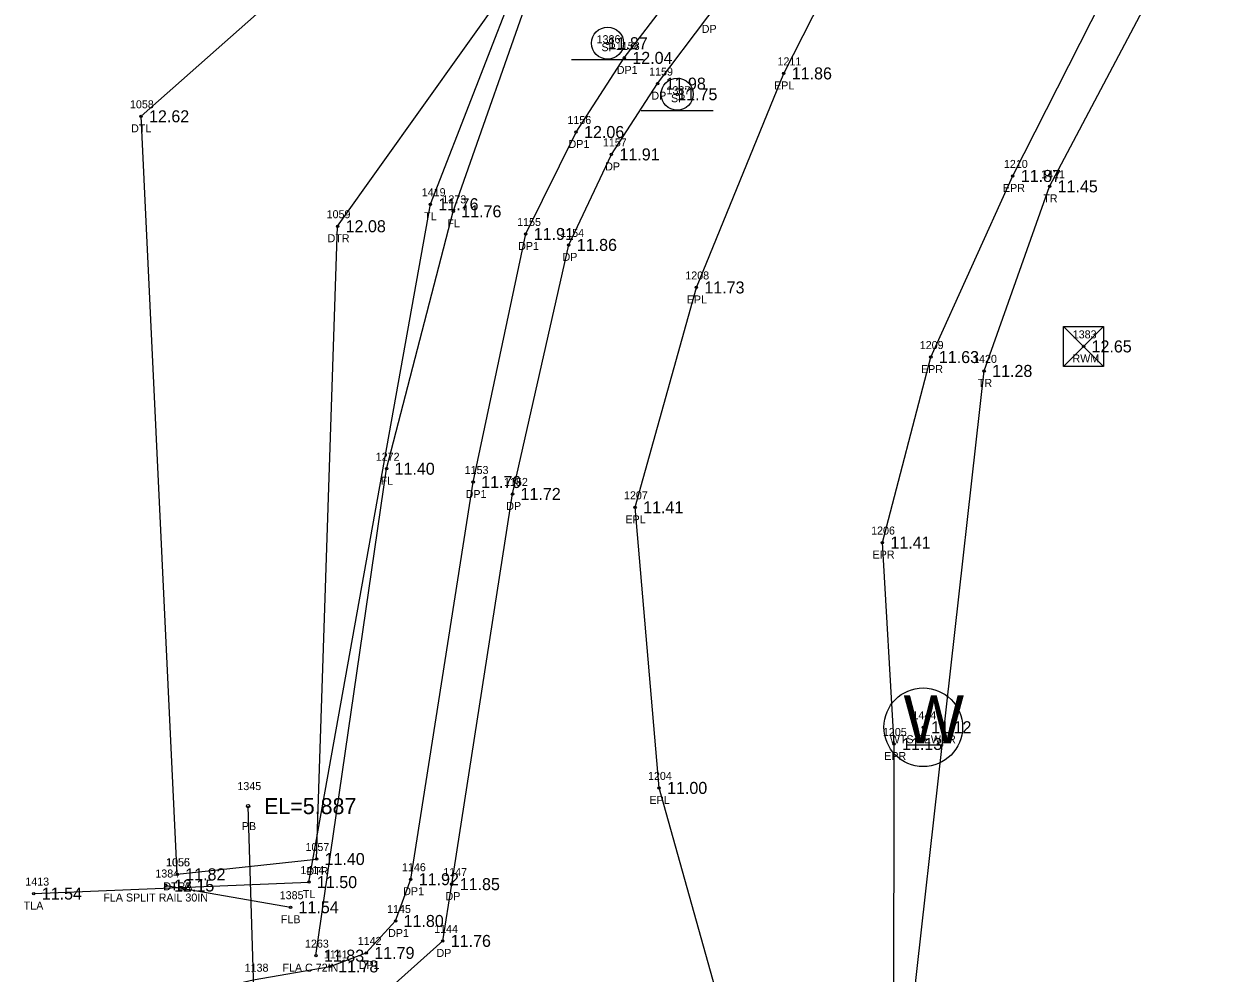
# Model space of a CAD drawing. Extents: x 2072307 to 2072993, y 127574 to 129736.
# Drawn here: x 2072680.7 to 2072830.3, y 128354.3 to 128472.9 of the extents above; entities that cross this region are included whole.
import ezdxf

# ---------------------------------------------------------------- set-up
doc = ezdxf.new("R2010")
doc.units = 0
for name, color, linetype in [('RD_EX_BldgApp', 7, 'Continuous'), ('RD_EX_BldgApp_txCode', 7, 'Continuous'), ('RD_EX_DR_Pipe', 7, 'Continuous'), ('RD_EX_DR_Pipe_txCode', 7, 'Continuous'), ('RD_EX_Driveway', 7, 'Continuous'), ('RD_EX_Driveway_txCode', 7, 'Continuous'), ('RD_EX_Fence_Other', 7, 'Continuous'), ('RD_EX_Fence_Other_txCode', 7, 'Continuous'), ('RD_EX_H2O', 7, 'Continuous'), ('RD_EX_H2O_txCode', 7, 'Continuous'), ('RD_EX_Road', 7, 'Continuous'), ('RD_EX_Road_txCode', 7, 'Continuous'), ('RD_EX_RW', 7, 'Continuous'), ('RD_EX_RW_TxCode', 7, 'Continuous'), ('RD_EX_TX_BldgApp_ELEV', 7, 'Continuous'), ('RD_EX_TX_Driveway_ELEV', 7, 'Continuous'), ('RD_EX_TX_Fence_Other_ELEV', 7, 'Continuous'), ('RD_EX_TX_H2O_ELEV', 7, 'Continuous'), ('RD_EX_TX_Road_ELEV', 7, 'Continuous'), ('RD_EX_TX_RW_ELEV', 7, 'Continuous'), ('RD_EX_TX_UT_ELEV', 7, 'Continuous'), ('RD_EX_TX_VEG_ELEV', 7, 'Continuous'), ('RD_EX_UT', 7, 'Continuous'), ('RD_EX_UT_txCode', 7, 'Continuous'), ('RD_EX_VEG', 7, 'Continuous'), ('RD_EX_VEG_txCode', 7, 'Continuous'), ('RD_SMD_Locator', 7, 'Continuous'), ('RD_TX_Pipe_ElevEX', 7, 'Continuous')]:
    doc.layers.add(name, color=color, linetype=linetype)

msp = doc.modelspace()

# ---------------------------------------------------------------- linework, layer by layer
at = {"layer": 'RD_EX_BldgApp'}
for p, q in [((2072749.16, 128468.44), (2072758.16, 128468.44)), ((2072757.86, 128462.07), (2072766.86, 128462.07))]:
    msp.add_line(p, q, dxfattribs=at)
for centre in [(2072753.67, 128470.46), (2072762.37, 128464.09)]:
    msp.add_circle(centre, 2, dxfattribs=at)
at = {"layer": 'RD_EX_DR_Pipe'}
msp.add_line((2072711.77, 128278.7), (2072708.75, 128375.17), dxfattribs=at)
at = {"layer": 'RD_EX_Driveway'}
for points in [[(2072694.21, 128239.74), (2072695.7, 128289.15), (2072695.56, 128330.43), (2072696.37, 128337.85), (2072700.81, 128345.17), (2072711.22, 128347.96), (2072719.56, 128349.59), (2072725.15, 128351.26), (2072733.07, 128358.33), (2072734.19, 128365.42), (2072741.79, 128414.16), (2072748.82, 128445.27), (2072754.15, 128456.57), (2072759.92, 128465.41), (2072766.21, 128473.75), (2072780.47, 128491.8), (2072796.27, 128516), (2072809.9, 128540.1), (2072821.01, 128555.78)], [(2072689.37, 128239.9), (2072690.93, 128289.43), (2072690.32, 128330.24), (2072690.73, 128338.81), (2072697.63, 128350.77), (2072709.38, 128353.48), (2072719, 128355.15), (2072723.52, 128356.83), (2072727.18, 128360.82), (2072729.07, 128366.04), (2072736.87, 128415.65), (2072743.44, 128446.63), (2072749.73, 128459.37), (2072755.76, 128468.63), (2072761.76, 128476.56), (2072776.61, 128495.01), (2072792.09, 128518.96), (2072805.19, 128542.59), (2072810.66, 128554.44), (2072797.46, 128551.01)]]:
    msp.add_lwpolyline(points, dxfattribs=at)
at = {"layer": 'RD_EX_Fence_Other'}
msp.add_line((2072698.5, 128365.25), (2072714.05, 128362.54), dxfattribs=at)
msp.add_lwpolyline([(2072717.23, 128356.49), (2072726.05, 128417.31), (2072734.38, 128449.46), (2072744.93, 128479.47), (2072775.22, 128496.41), (2072780.14, 128517.18), (2072757.78, 128516.55), (2072777.16, 128556.96), (2072786.53, 128575.88)], dxfattribs=at)
at = {"layer": 'RD_EX_H2O'}
for points in [[(2072699.9, 128366.65), (2072695.37, 128461.33), (2072737.55, 128498.66), (2072764.73, 128514.82)], [(2072699.9, 128366.65), (2072717.3, 128368.56), (2072719.94, 128447.6), (2072741.08, 128477.29), (2072773.98, 128508.7), (2072764.73, 128514.82)]]:
    msp.add_lwpolyline(points, dxfattribs=at)
at = {"layer": 'RD_EX_Road'}
for points in [[(2072789.45, 128345.69), (2072789.46, 128382.93), (2072788.01, 128408.09), (2072794.06, 128431.26), (2072804.3, 128453.88), (2072840.7, 128525.64), (2072876.68, 128596.08), (2072888.72, 128617.36), (2072893.24, 128622.62), (2072899.84, 128627.36), (2072910.72, 128631.76), (2072918.79, 128632.23), (2072935.82, 128627.02), (2072957.37, 128619.98)], [(2072771.5, 128336.87), (2072760.1, 128377.44), (2072757.11, 128412.49), (2072764.76, 128439.95), (2072775.68, 128466.69), (2072812.91, 128539.86)]]:
    msp.add_lwpolyline(points, dxfattribs=at)
at = {"layer": 'RD_EX_RW'}
for p, q in [((2072810.64, 128430.09), (2072815.64, 128435.09)), ((2072815.64, 128430.09), (2072810.64, 128435.09)), ((2072815.64, 128435.09), (2072815.64, 128430.09))]:
    msp.add_line(p, q, dxfattribs=at)
msp.add_lwpolyline([(2072810.64, 128430.09), (2072810.64, 128435.09), (2072815.64, 128435.09), (2072815.64, 128430.09)], close=True, dxfattribs=at)
at = {"layer": 'RD_EX_UT'}
msp.add_line((2072790.98, 128382.81), (2072795.61, 128382.81), dxfattribs=at)
msp.add_circle((2072793.11, 128385.02), 4.91, dxfattribs=at)
at = {"layer": 'RD_EX_VEG'}
for points in [[(2072791.29, 128345.62), (2072800.72, 128429.53), (2072808.9, 128452.58), (2072870.32, 128568.64), (2072876.57, 128573.6), (2072916.77, 128564.68), (2072920.97, 128548.67)], [(2072681.97, 128364.24), (2072716.35, 128365.68), (2072731.52, 128450.35), (2072742.94, 128479.7), (2072773.31, 128497.01), (2072778.81, 128515.7), (2072758.24, 128515.09)]]:
    msp.add_lwpolyline(points, dxfattribs=at)
at = {"layer": 'RD_SMD_Locator'}
for centre, radius in [((2072753.67, 128470.46), 0.15), ((2072755.76, 128468.63), 0.15), ((2072775.68, 128466.69), 0.15), ((2072759.92, 128465.41), 0.15), ((2072762.37, 128464.09), 0.15), ((2072695.37, 128461.33), 0.15), ((2072749.73, 128459.37), 0.15), ((2072754.15, 128456.57), 0.15), ((2072804.3, 128453.88), 0.15), ((2072808.9, 128452.58), 0.15), ((2072731.52, 128450.35), 0.15), ((2072734.38, 128449.46), 0.15), ((2072719.94, 128447.6), 0.15), ((2072743.44, 128446.63), 0.15), ((2072748.82, 128445.27), 0.15), ((2072764.76, 128439.95), 0.15), ((2072813.14, 128432.59), 0.15), ((2072794.06, 128431.26), 0.15), ((2072800.72, 128429.53), 0.15), ((2072726.05, 128417.31), 0.15), ((2072736.87, 128415.65), 0.15), ((2072741.79, 128414.16), 0.15), ((2072757.11, 128412.49), 0.15), ((2072788.01, 128408.09), 0.15), ((2072793.11, 128385.02), 0.15), ((2072789.46, 128382.93), 0.15), ((2072760.1, 128377.44), 0.15), ((2072708.75, 128375.17), 0.2), ((2072717.3, 128368.56), 0.15), ((2072699.9, 128366.65), 0.15), ((2072699.9, 128366.65), 0.15), ((2072698.5, 128365.25), 0.15), ((2072716.35, 128365.68), 0.15), ((2072729.07, 128366.04), 0.15), ((2072734.19, 128365.42), 0.15), ((2072681.97, 128364.24), 0.15), ((2072714.05, 128362.54), 0.15), ((2072727.18, 128360.82), 0.15), ((2072733.07, 128358.33), 0.15), ((2072717.23, 128356.49), 0.15), ((2072723.52, 128356.83), 0.15), ((2072719, 128355.15), 0.15)]:
    msp.add_circle(centre, radius, dxfattribs=at)

# ---------------------------------------------------------------- texts
at = {"layer": 'RD_EX_BldgApp_txCode'}
for s, p in [('1386', (2072752.3, 128470.46)), ('SP', (2072752.9, 128469.46)), ('1387', (2072761.03, 128464.09)), ('SP', (2072761.59, 128463.09))]:
    msp.add_text(s, height=1, dxfattribs=at).set_placement(p)
at = {"layer": 'RD_EX_DR_Pipe_txCode'}
for s, p in [('1345', (2072707.41, 128377.17)), ('PB', (2072707.97, 128372.17))]:
    msp.add_text(s, height=1, dxfattribs=at).set_placement(p)
at = {"layer": 'RD_EX_Driveway_txCode'}
for s, p in [('DP', (2072765.43, 128471.75)), ('1158', (2072754.7, 128469.63)), ('DP1', (2072754.82, 128466.63)), ('1159', (2072758.86, 128466.41)), ('DP', (2072759.14, 128463.41)), ('1156', (2072748.65, 128460.37)), ('DP1', (2072748.79, 128457.37)), ('1157', (2072753.08, 128457.57)), ('DP', (2072753.37, 128454.57)), ('1155', (2072742.37, 128447.63)), ('1154', (2072747.76, 128446.27)), ('DP1', (2072742.49, 128444.63)), ('DP', (2072748.04, 128443.27)), ('1153', (2072735.81, 128416.65)), ('1152', (2072740.73, 128415.16)), ('DP1', (2072735.93, 128413.65)), ('DP', (2072741.01, 128412.16)), ('1146', (2072727.98, 128367.04)), ('1147', (2072733.13, 128366.42)), ('DP1', (2072728.13, 128364.04)), ('DP', (2072733.42, 128363.42)), ('1145', (2072726.12, 128361.82)), ('1144', (2072732, 128359.33)), ('1142', (2072722.45, 128357.83)), ('DP1', (2072726.24, 128358.82)), ('DP', (2072732.29, 128356.33)), ('1141', (2072718.22, 128356.15)), ('DP1', (2072722.57, 128354.83)), ('1138', (2072708.32, 128354.48))]:
    msp.add_text(s, height=1, dxfattribs=at).set_placement(p)
at = {"layer": 'RD_EX_Fence_Other_txCode'}
for s, p in [('1273', (2072733.03, 128450.46)), ('FL', (2072733.65, 128447.46)), ('1272', (2072724.7, 128418.31)), ('FL', (2072725.31, 128415.31)), ('1384', (2072697.16, 128366.25)), ('FLA SPLIT RAIL 30IN', (2072690.66, 128363.25)), ('1385', (2072712.7, 128363.54)), ('FLB', (2072712.84, 128360.54)), ('1263', (2072715.86, 128357.49)), ('FLA C 72IN', (2072713.04, 128354.49))]:
    msp.add_text(s, height=1, dxfattribs=at).set_placement(p)
at = {"layer": 'RD_EX_H2O_txCode'}
for s, p in [('1058', (2072693.99, 128462.33)), ('DTL', (2072694.13, 128459.33)), ('1059', (2072718.56, 128448.6)), ('DTR', (2072718.68, 128445.6)), ('1057', (2072715.92, 128369.56)), ('1056', (2072698.49, 128367.65)), ('1055', (2072698.52, 128367.65)), ('DTR', (2072716.03, 128366.56)), ('DTRA', (2072698.15, 128364.65)), ('DTLA', (2072698.17, 128364.65))]:
    msp.add_text(s, height=1, dxfattribs=at).set_placement(p)
at = {"layer": 'RD_EX_Road_txCode'}
for s, p in [('1211', (2072774.9, 128467.69)), ('EPL', (2072774.47, 128464.69)), ('1210', (2072803.19, 128454.88)), ('EPR', (2072803.07, 128451.88)), ('1208', (2072763.38, 128440.95)), ('EPL', (2072763.56, 128437.95)), ('1209', (2072792.68, 128432.26)), ('EPR', (2072792.83, 128429.26)), ('1207', (2072755.72, 128413.49)), ('EPL', (2072755.9, 128410.49)), ('1206', (2072786.6, 128409.09)), ('EPR', (2072786.78, 128406.09)), ('1205', (2072788.07, 128383.93)), ('EPR', (2072788.23, 128380.93)), ('1204', (2072758.72, 128378.44)), ('EPL', (2072758.9, 128375.44))]:
    msp.add_text(s, height=1, dxfattribs=at).set_placement(p)
at = {"layer": 'RD_EX_RW_TxCode'}
for s, p in [('1383', (2072811.79, 128433.59)), ('RWM', (2072811.76, 128430.59))]:
    msp.add_text(s, height=1, dxfattribs=at).set_placement(p)
at = {"layer": 'RD_EX_TX_BldgApp_ELEV'}
for s, p in [('11.87', (2072753.67, 128469.71)), ('11.75', (2072762.37, 128463.34))]:
    msp.add_text(s, height=1.5, dxfattribs=at).set_placement(p)
at = {"layer": 'RD_EX_TX_Driveway_ELEV'}
for s, p in [('12.04', (2072756.76, 128467.88)), ('11.98', (2072760.92, 128464.66)), ('12.06', (2072750.73, 128458.62)), ('11.91', (2072755.15, 128455.82)), ('11.91', (2072744.44, 128445.88)), ('11.86', (2072749.82, 128444.52)), ('11.79', (2072737.87, 128414.9)), ('11.72', (2072742.79, 128413.41)), ('11.92', (2072730.07, 128365.29)), ('11.85', (2072735.19, 128364.67)), ('11.80', (2072728.18, 128360.07)), ('11.76', (2072734.07, 128357.58)), ('11.79', (2072724.52, 128356.08)), ('11.78', (2072720, 128354.4))]:
    msp.add_text(s, height=1.5, dxfattribs=at).set_placement(p)
at = {"layer": 'RD_EX_TX_Fence_Other_ELEV'}
for s, p in [('11.76', (2072735.38, 128448.71)), ('11.40', (2072727.05, 128416.56)), ('12.15', (2072699.5, 128364.5)), ('11.54', (2072715.05, 128361.79)), ('11.83', (2072718.23, 128355.74))]:
    msp.add_text(s, height=1.5, dxfattribs=at).set_placement(p)
at = {"layer": 'RD_EX_TX_H2O_ELEV'}
for s, p in [('12.62', (2072696.37, 128460.58)), ('12.08', (2072720.94, 128446.85)), ('11.40', (2072718.3, 128367.81)), ('11.82', (2072700.9, 128365.9)), ('11.82', (2072700.9, 128365.9))]:
    msp.add_text(s, height=1.5, dxfattribs=at).set_placement(p)
at = {"layer": 'RD_EX_TX_Road_ELEV'}
for s, p in [('11.86', (2072776.68, 128465.94)), ('11.87', (2072805.3, 128453.13)), ('11.73', (2072765.76, 128439.2)), ('11.63', (2072795.06, 128430.51)), ('11.41', (2072758.11, 128411.74)), ('11.41', (2072789.01, 128407.34)), ('11.13', (2072790.46, 128382.18)), ('11.00', (2072761.1, 128376.69))]:
    msp.add_text(s, height=1.5, dxfattribs=at).set_placement(p)
at = {"layer": 'RD_EX_TX_RW_ELEV'}
msp.add_text('12.65', height=1.5, dxfattribs=at).set_placement((2072814.14, 128431.84))
at = {"layer": 'RD_EX_TX_UT_ELEV'}
msp.add_text('11.12', height=1.5, dxfattribs=at).set_placement((2072794.11, 128384.27))
at = {"layer": 'RD_EX_TX_VEG_ELEV'}
for s, p in [('11.45', (2072809.9, 128451.83)), ('11.76', (2072732.52, 128449.6)), ('11.28', (2072801.72, 128428.78)), ('11.50', (2072717.35, 128364.93)), ('11.54', (2072682.97, 128363.49))]:
    msp.add_text(s, height=1.5, dxfattribs=at).set_placement(p)
at = {"layer": 'RD_EX_UT'}
msp.add_text('W', height=6, dxfattribs=at).set_placement((2072790.64, 128383.02))
at = {"layer": 'RD_EX_UT_txCode'}
for s, p in [('1444', (2072791.76, 128386.02)), ('WTS SEWER', (2072788.93, 128383.02))]:
    msp.add_text(s, height=1, dxfattribs=at).set_placement(p)
at = {"layer": 'RD_EX_VEG_txCode'}
for s, p in [('1421', (2072807.84, 128453.58)), ('1419', (2072730.45, 128451.35)), ('TR', (2072808.11, 128450.58)), ('TL', (2072730.74, 128448.35)), ('1420', (2072799.34, 128430.53)), ('TR', (2072799.93, 128427.53)), ('1413', (2072680.91, 128365.24)), ('1414', (2072715.29, 128366.68)), ('TLA', (2072680.71, 128362.24)), ('TL', (2072715.58, 128363.68))]:
    msp.add_text(s, height=1, dxfattribs=at).set_placement(p)
at = {"layer": 'RD_TX_Pipe_ElevEX'}
msp.add_text('EL=5.887', height=2, dxfattribs=at).set_placement((2072710.75, 128374.17))

doc.saveas('drawing.dxf')
